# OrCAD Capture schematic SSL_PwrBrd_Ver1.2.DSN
size Custom; rev: 1.0
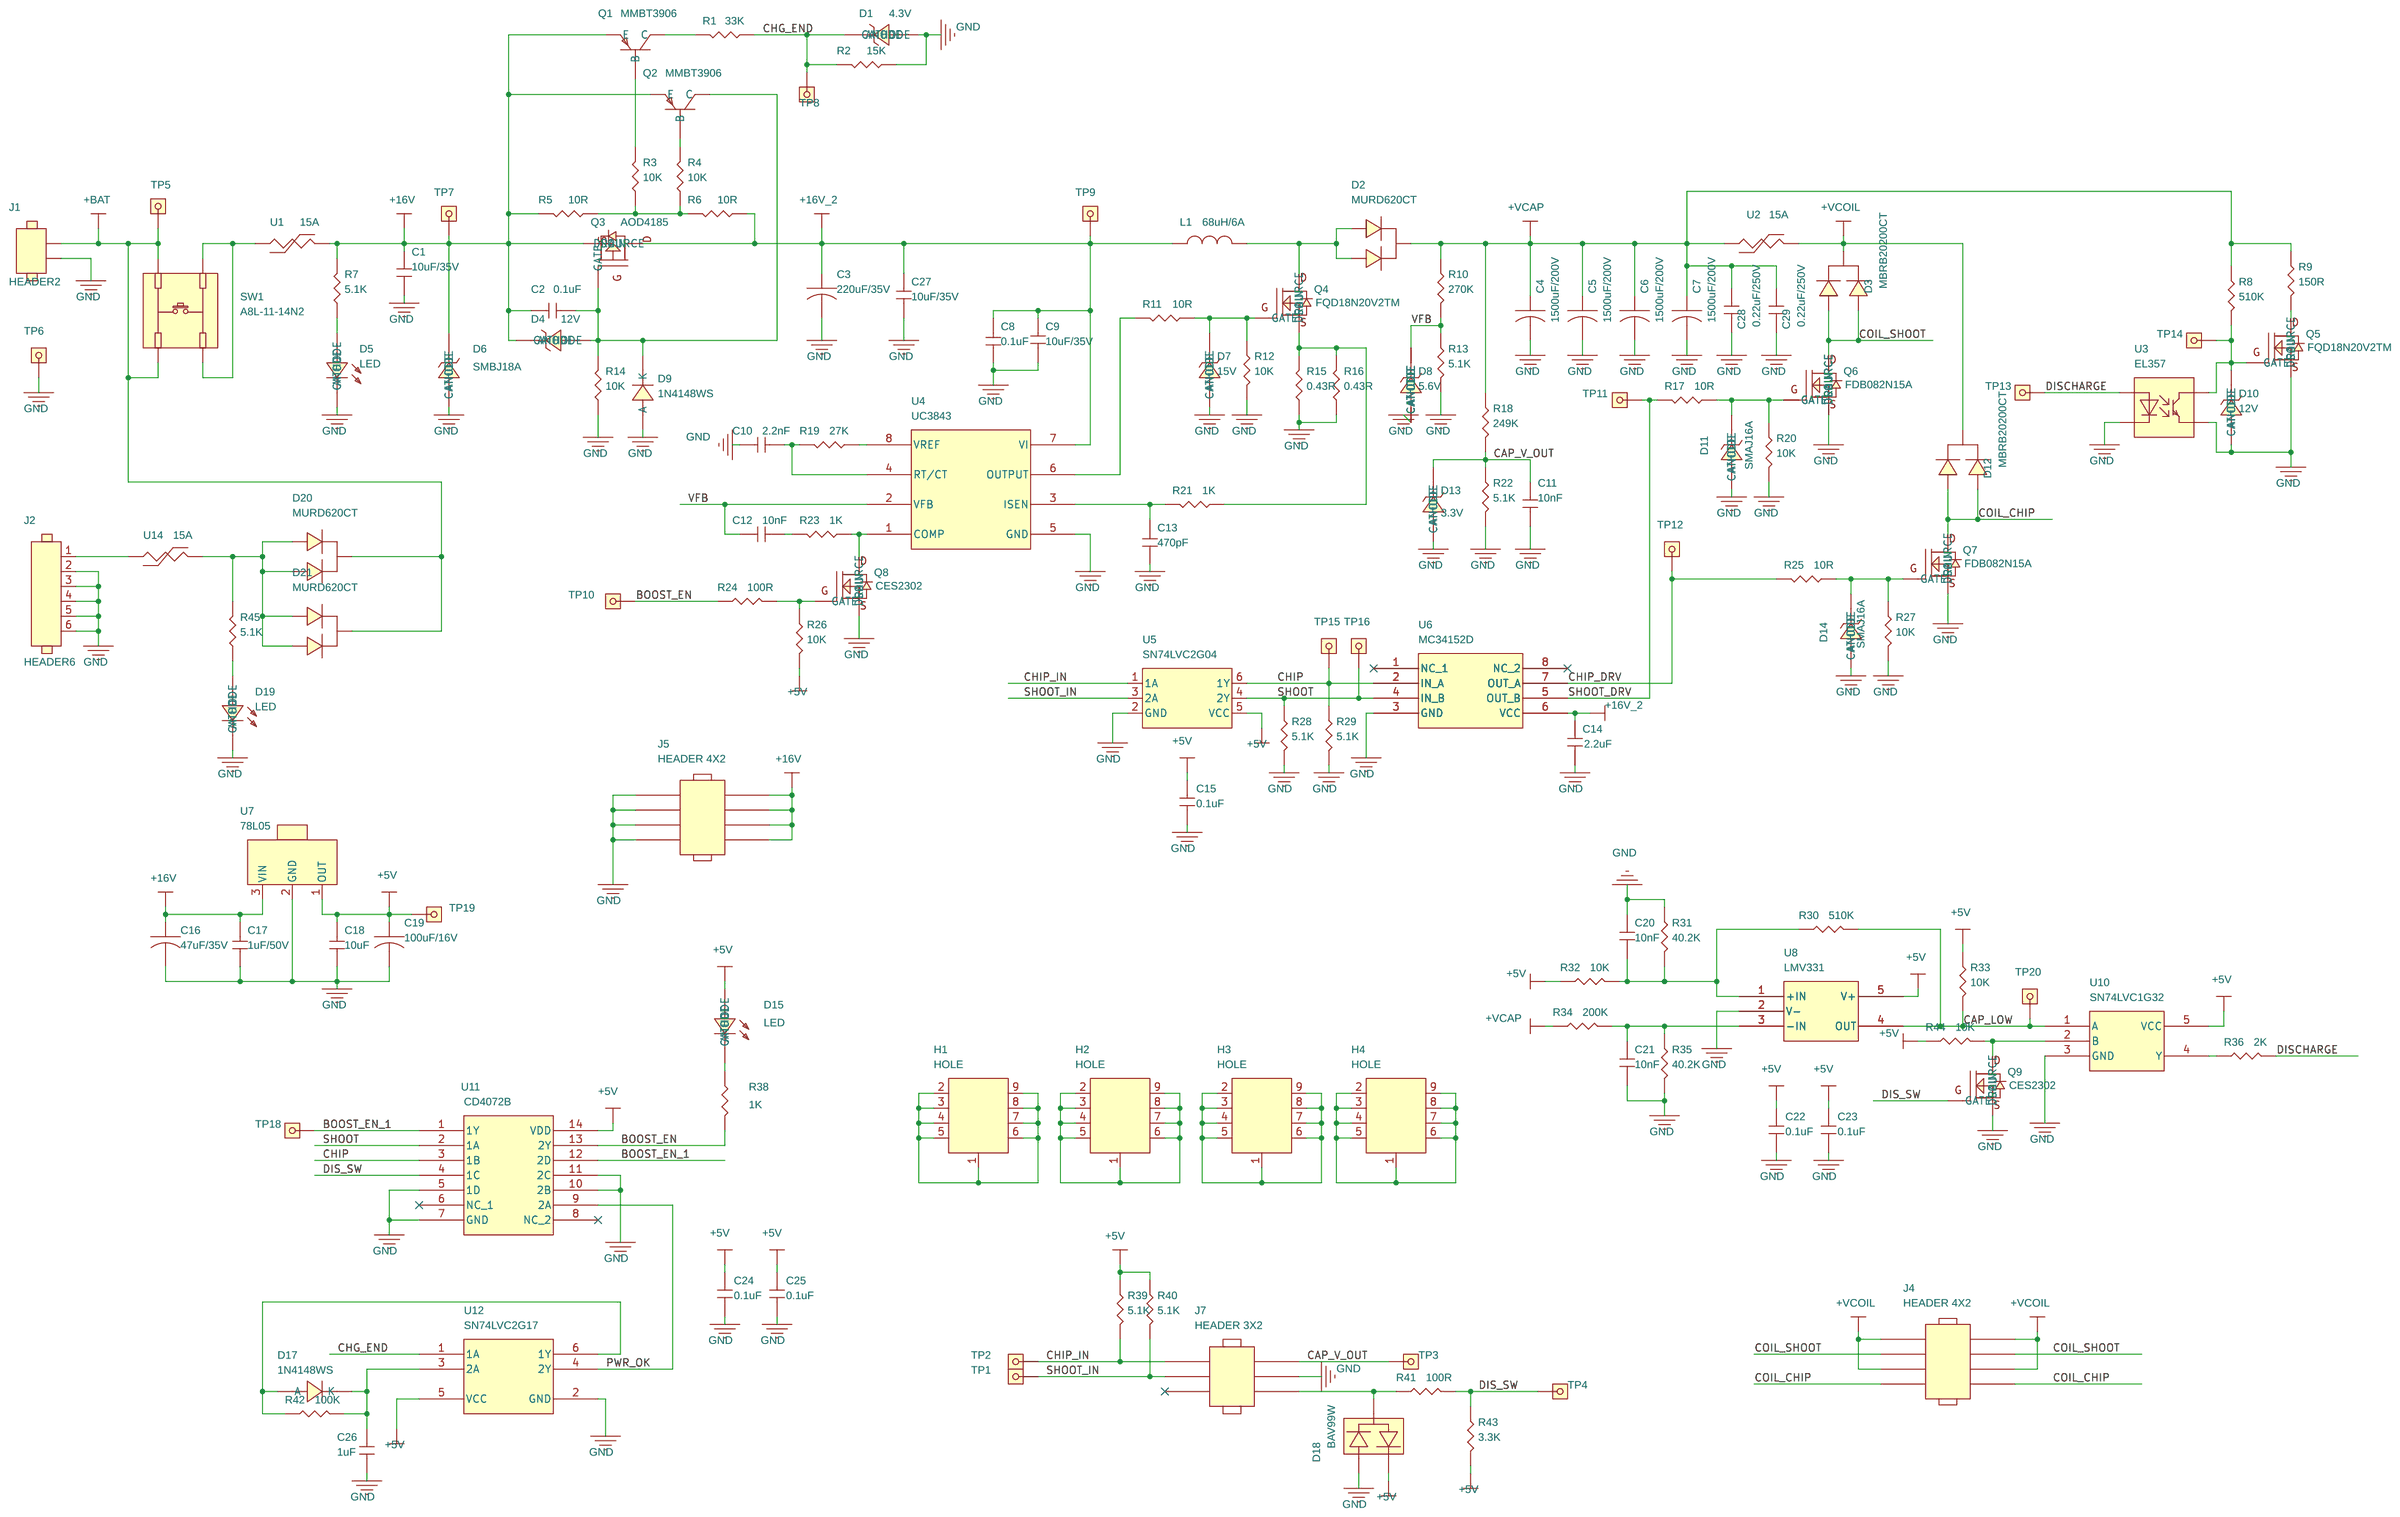
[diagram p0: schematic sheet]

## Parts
C1  10uF/35V  [1206_C]
C2  0.1uF  [0603_C]
C3  220uF/35V  [cap_e_smd_315]
C4  1500uF/200V  [EC-35]
C5  1500uF/200V  [EC-35]
C6  1500uF/200V  [EC-35]
C7  1500uF/200V  [EC-35]
C8  0.1uF  [0603_C]
C9  10uF/35V  [1206_C]
C10  2.2nF  [0603_C]
C11  10nF  [0603_C]
C12  10nF  [0603_C]
C13  470pF  [0603_C]
C14  2.2uF  [0603_C]
C15  0.1uF  [0603_C]
C16  47uF/35V  [cap_e_smd_250]
C17  1uF/50V  [0603_C]
C18  10uF  [0805_C]
C19  100uF/16V  [cap_e_smd_250]
C20  10nF  [0603_C]
C21  10nF  [0603_C]
C22  0.1uF  [0603_C]
C23  0.1uF  [0603_C]
C24  0.1uF  [0603_C]
C25  0.1uF  [0603_C]
C26  1uF  [0603_C]
C27  10uF/35V  [1206_C]
C28  0.22uF/250V  [1210_C]
C29  0.22uF/250V  [1210_C]
D1  4.3V  [SOD-123]
D2  MURD620CT  [TO252AA]
D3  MBRB20200CT  [TO263-2]
D4  12V  [SOD-123]
D5  LED  [0603_LED]
D6  SMBJ18A  [SMB]
D7  15V  [SOD-123]
D8  5.6V  [SOD-123]
D9  1N4148WS  [SOD-323]
D10  12V  [SOD-123]
D11  SMAJ16A  [SMB]
D12  MBRB20200CT  [TO263-2]
D13  3.3V  [SOD-123]
D14  SMAJ16A  [SMB]
D15  LED  [0603_LED]
D17  1N4148WS  [SOD-323]
D18  BAV99W  [SC70]
D19  LED  [0603_LED]
D20  MURD620CT  [TO252AA]
D21  MURD620CT  [TO252AA]
H1  HOLE  [HOLE_3]
H2  HOLE  [HOLE_3]
H3  HOLE  [HOLE_3]
H4  HOLE  [HOLE_3]
J1  HEADER2  [XT30PW-M]
J2  HEADER6  [power_dc2_5mm]
J4  HEADER 4X2  [SPT1_5-4P-H-3_5]
J5  HEADER 4X2  [HDR254MW-2X4]
J7  HEADER 3X2  [HDR254MW-2X3]
L1  68uH/6A  [L_DO5040H]
Q1  MMBT3906  [SOT23]
Q2  MMBT3906  [SOT23]
Q3  AOD4185  [TO252AA]
Q4  FQD18N20V2TM  [TO252AA]
Q5  FQD18N20V2TM  [TO252AA]
Q6  FDB082N15A  [TO263-2]
Q7  FDB082N15A  [TO263-2]
Q8  CES2302  [SOT23]
Q9  CES2302  [SOT23]
R1  33K  [0603_R]
R2  15K  [0603_R]
R3  10K  [0603_R]
R4  10K  [0603_R]
R5  10R  [2512_R]
R6  10R  [2512_R]
R7  5.1K  [0603_R]
R8  510K  [1206_R]
R9  150R  [Res_5W]
R10  270K  [1206_R]
R11  10R  [0603_R]
R12  10K  [0603_R]
R13  5.1K  [0603_R]
R14  10K  [0603_R]
R15  0.43R  [2512_R]
R16  0.43R  [2512_R]
R17  10R  [0603_R]
R18  249K  [1206_R]
R19  27K  [0603_R]
R20  10K  [0603_R]
R21  1K  [0603_R]
R22  5.1K  [0603_R]
R23  1K  [0603_R]
R24  100R  [0603_R]
R25  10R  [0603_R]
R26  10K  [0603_R]
R27  10K  [0603_R]
R28  5.1K  [0603_R]
R29  5.1K  [0603_R]
R30  510K  [0603_R]
R31  40.2K  [0603_R]
R32  10K  [0603_R]
R33  10K  [0603_R]
R34  200K  [1206_R]
R35  40.2K  [0603_R]
R36  2K  [0603_R]
R38  1K  [0603_R]
R39  5.1K  [0603_R]
R40  5.1K  [0603_R]
R41  100R  [0603_R]
R42  100K  [0603_R]
R43  3.3K  [0603_R]
R44  10K  [0603_R]
R45  5.1K  [0603_R]
SW1  A8L-11-14N2  [A8L-11-14N2]
TP1  TP  [TP6]
TP2  TP  [TP6]
TP3  TP  [TP6]
TP4  TP  [TP6]
TP5  TP  [TP6]
TP6  TP  [TP6]
TP7  TP  [TP6]
TP8  TP  [TP6]
TP9  TP  [TP6]
TP10  TP  [TP6]
TP11  TP  [TP6]
TP12  TP  [TP6]
TP13  TP  [TP6]
TP14  TP  [TP6]
TP15  TP  [TP6]
TP16  TP  [TP6]
TP18  TP  [TP6]
TP19  TP  [TP6]
TP20  TP  [TP6]
U1  15A  [1808_F_Socket]
U2  15A  [1808_F_Socket]
U3  EL357  [PC357]
U4  UC3843  [SO-8]
U5  SN74LVC2G04  [SOT23-6]
U6  MC34152D  [SO-8]
U7  78L05  [sot89-3]
U8  LMV331  [SOT23-5]
U10  SN74LVC1G32  [SOT23-5]
U11  CD4072B  [SO-14]
U12  SN74LVC2G17  [SOT23-6]
U14  15A  [1808_F_Socket]

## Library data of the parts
C1 C9 C27-C29 = CAP_NP: 瓷片电容，20%，X5R, 35V, 1206; Part Number: 通用; Vendor: 通用
C2 C8 C10 C12 C13 C17 C18 = CAP_NP
C3-C7 C16 C19 = CAP_P: 电解电容, 35V, 100uF, SMD, 6.3mm; Part Number: 通用; Vendor: NICHICON
C11 C14 C15 C20-C26 = CAP_NP: 瓷片电容，20%，X5R, 25V, 0603; Part Number: 通用; Vendor: 通用
D1 D4 = ZENER
D2 D20 D21 = DIODE_DUAL_CC: Part Number: MURD620CTT4G; Vendor: OnSemi
D3 D12 = DIODE_DUAL_CC
D5 D19 = LED
D6 = ZENER: TVS; ROOM: M3; Vendor: 通用
D7 D8 D10 D11 D13 D14 = ZENER: TVS; Part Number: SMBJ18A; ROOM: M3; Vendor: 通用
D9 D17 = DIODE
D15 = LED: LED, 0603, Orange; Part Number: 通用; Vendor: 通用
D18 = DIODE_2X_S_SOT23: Diode; Part Number: BAV99WT1G; Vendor: OnSemi
H1-H4 = HOLE: 安装孔; Part Number: 通用; Vendor: 通用
J1 = HEADER2
J2 = HEADER6
J4 J5 = HEADER_4X2
J7 = HEADER_3X2
L1 = L: Inductor, 6A; Part Number: DO5040H-683MLD; Vendor: Coilcraft
Q1 Q2 = PNP,SOT23
Q3 = PMOS,SOT23
Q4-Q9 = NMOS,SOT23
R1-R7 R9-R27 R30-R36 R38-R45 = RES_2
R8 R28 R29 = RES_2: SMD通用电阻，1%，1/16W, 0603; Part Number: 通用; Vendor: 通用
SW1 = SW_6
TP1-TP16 TP18-TP20 = TP: 测试点; Part Number: 通用; Vendor: 通用
U1 U2 U14 = FUSE
U3 = PC357: 光耦; Part Number: EL357N; Vendor: 亿光
U4 = UC3842
U5 = SN74LVC2G04
U6 = MC34152D: Vendor: OnSemi
U7 = 78L15_SOT89: Part Number: L78L05ACUTR
U8 = LMV331
U10 = SN74LVC1G32
U11 = CD4072B
U12 = SN74LVC2G17

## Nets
+5V: C15.1 C18.2 C19.1 C22.1 C23.1 C24.1 C25.1 D15.1(ANODE) D18.2 R26.1 R32.2 R33.2 R39.2 R40.2 R43.1 R44.2 TP19.1 U5.5(VCC) U7.1(OUT) U8.5(V+) U10.5(VCC) U11.14(VDD) U12.5(VCC)
+16V: C1.1 C2.1 C16.1 C17.2 D4.2(CATHODE) D6.2(CATHODE) J5.2 J5.4 J5.6 J5.8 Q1.2(E) Q2.2(E) Q3.2(SOURCE) R5.1 R7.1 TP7.1 U1.2 U7.3(VIN)
+16V_2: C3.1 C8.2 C9.1 C14.1 C27.1 L1.1 Q3.3(DRAIN) R6.2 TP9.1 U4.7(VI) U6.6(VCC)
GND: C1.2 C3.2 C4.2 C5.2 C6.2 C7.2 C8.1 C9.2 C10.1 C11.2 C13.1 C14.2 C15.2 C16.2 C17.1 C18.1 C19.2 C20.1 C21.2 C22.2 C23.2 C24.2 C25.2 C26.2 C27.2 C28.2 C29.2 D1.1(ANODE) D5.2(CATHODE) D6.1(ANODE) D7.1(ANODE) D8.1(ANODE) D9.1(A) D10.1(ANODE) D11.1(ANODE) D13.1(ANODE) D14.1(ANODE) D18.1 D19.2(CATHODE) J1.2 J2.2 J2.3 J2.4 J2.5 J2.6 J5.1 J5.3 J5.5 J5.7 J7.4 Q5.2(SOURCE) Q6.2(SOURCE) Q7.2(SOURCE) Q8.2(SOURCE) Q9.2(SOURCE) R2.2 R12.1 R13.1 R14.2 R15.2 R16.2 R20.1 R22.1 R27.1 R28.1 R29.1 R31.2 R35.1 TP6.1 U3.2 U3.3 U4.5(GND) U5.2(GND) U6.3(GND) U7.2(GND) U8.2(V-) U10.3(GND) U11.5(1D) U11.7(GND) U11.10(2B) U11.11(2C) U12.2(GND)
+BAT: D20.3 D21.3 J1.1 SW1.1 SW1.3 TP5.1
+VCAP: C4.1 C5.1 C6.1 C7.1 C28.1 C29.1 D2.3 R8.2 R9.2 R10.2 R18.2 R34.2 U2.1
+VCOIL: D3.3 D12.3 J4.1 J4.2 J4.5 J4.6 U2.2
BOOST_EN: R24.2 R38.1 TP10.1 U11.13(2Y)
BOOST_EN_1: TP18.1 U11.1(1Y) U11.12(2D)
CAP_LOW: R30.1 R33.1 TP20.1 U8.4(OUT) U10.1(A)
CAP_V_OUT: C11.1 D13.2(CATHODE) J7.2 R18.1 R22.2 TP3.1
CHG_END: D1.2(CATHODE) R1.2 R2.1 TP8.1 U12.1(1A)
CHIP: R29.2 TP15.1 U5.6(1Y) U6.2(IN_A) U11.3(1B)
CHIP_DRV: R25.1 TP12.1 U6.7(OUT_A)
CHIP_IN: J7.1 R39.1 TP2.1 U5.1(1A)
COIL_CHIP: D12.1 D12.2 J4.7 J4.8 Q7.3(DRAIN)
COIL_SHOOT: D3.1 D3.2 J4.3 J4.4 Q6.3(DRAIN)
DIS_SW: Q9.1(GATE) R41.1 R43.2 TP4.1 U11.4(1C)
DISCHARGE: R36.1 TP13.1 U3.1
PWR_OK: U11.9(2A) U12.4(2Y)
SHOOT: R28.2 TP16.1 U5.4(2Y) U6.4(IN_B) U11.2(1A)
SHOOT_DRV: R17.1 TP11.1 U6.5(OUT_B)
SHOOT_IN: J7.3 R40.1 TP1.1 U5.3(2A)
VFB: C12.1 D8.2(CATHODE) R10.1 R13.2 U4.2(VFB)
N00647: C2.2 D4.1(ANODE) D9.2(K) Q2.3(C) Q3.1(GATE) R14.1
N02314: R3.2 R4.2 R5.2 R6.1
N04713: Q2.1(B) R4.1
N04752: Q1.1(B) R3.1
N05183: Q1.3(C) R1.1
N5273417: D5.1(ANODE) R7.2
N5276714: R19.2 U4.8(VREF)
N5277105: C10.2 R19.1 U4.4(RT/CT)
N5278068: Q8.3(DRAIN) R23.2 U4.1(COMP)
N5278284: C12.2 R23.1
N5280051: Q8.1(GATE) R24.1 R26.2
N11462968: D2.1 D2.2 L1.2 Q4.3(DRAIN)
N11463163: Q4.2(SOURCE) R15.1 R16.1 R21.2
N11464709: D7.2(CATHODE) Q4.1(GATE) R11.2 R12.2
N11468710: R11.1 U4.6(OUTPUT)
N11471960: C13.2 R21.1 U4.3(ISEN)
N11488509: D11.2(CATHODE) Q6.1(GATE) R17.2 R20.2
N11493133: D14.2(CATHODE) Q7.1(GATE) R25.2 R27.2
N11962195: Q5.3(DRAIN) R9.1
N11967817: D10.2(CATHODE) Q5.1(GATE) R8.1 TP14.1 U3.4
N12014213: C26.1 D17.2(K) R42.1 U12.3(2A)
N12020233: D17.1(A) R42.2 U12.6(1Y)
N12029339: D15.2(CATHODE) R38.2
N12095362: C21.1 R34.1 R35.2 U8.3(-IN)
N12099460: C20.2 R30.2 R31.1 R32.1 U8.1(+IN)
N12127491: Q9.3(DRAIN) R44.1 U10.2(B)
N12133632: R36.2 U10.4(Y)
N12190959: SW1.2 SW1.4 U1.1
N12237973: D18.3 J7.6 R41.2
N12300785: H1.1 H1.2 H1.3 H1.4 H1.5 H1.6 H1.7 H1.8 H1.9
N12300857: H2.1 H2.2 H2.3 H2.4 H2.5 H2.6 H2.7 H2.8 H2.9
N12300959: H3.1 H3.2 H3.3 H3.4 H3.5 H3.6 H3.7 H3.8 H3.9
N12301091: H4.1 H4.2 H4.3 H4.4 H4.5 H4.6 H4.7 H4.8 H4.9
N12384738: D19.1(ANODE) R45.2
N12384949: D20.1 D20.2 D21.1 D21.2 R45.1 U14.2
N12400429: J2.1 U14.1

Not connected (* = marked no-connect by the designer): J7 5*; U6 1(NC)* 8(NC_2)*; U11 6(NC_1)* 8(NC_2)*
